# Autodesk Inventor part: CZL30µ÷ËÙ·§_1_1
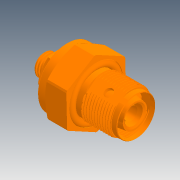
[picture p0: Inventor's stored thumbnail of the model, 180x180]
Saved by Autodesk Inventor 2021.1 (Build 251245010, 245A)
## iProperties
Created: 2021-05
Part Number: CZL30µ÷ËÙ·§_1_1
Material: Ogólny
Document SubType Name: Modeling
Designer: user
Density: 1 g/cm^3
Appearance: Domyślna
Author: user
Revision Number: ÈÎºÎ
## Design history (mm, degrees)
feature "Złożony1"
body "Srf1"
